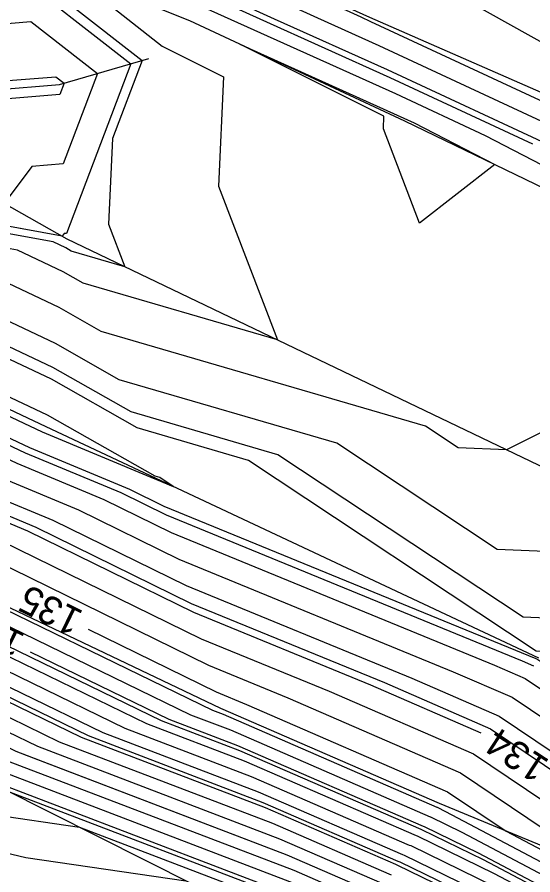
# Model space of a CAD drawing. Extents: x 2354170 to 2357230, y 866100 to 868290.
# Drawn here: x 2354998.2 to 2355034.8, y 867572.5 to 867633.4 of the extents above; entities that cross this region are included whole.
import ezdxf

# ---------------------------------------------------------------- set-up
doc = ezdxf.new("R2010")
doc.units = 0
for name, color, linetype in [('Default', 7, 'Continuous'), ('DTM Contours Major', 7, 'Continuous'), ('DTM Contours Major Text', 7, 'Continuous'), ('DTM Contours Minor', 7, 'Continuous'), ('PH Exist DTM Breakline', 7, 'Continuous')]:
    doc.layers.add(name, color=color, linetype=linetype)

msp = doc.modelspace()

# ---------------------------------------------------------------- linework, layer by layer
at = {"layer": 'Default'}
for points in [[(2355074.447, 867619.179), (2355074.154, 867619.39), (2355068.209, 867620.789), (2355051.797, 867622.962), (2355050.162, 867623.866), (2355048.755, 867624.16), (2355028.509, 867635.467), (2355025.079, 867637.946), (2355021.957, 867639.854), (2355009.227, 867645.813), (2355004.635, 867648.65), (2355001.188, 867649.633), (2354995.884, 867652.137), (2354991.371, 867653.721), (2354989.082, 867654.28), (2354986.916, 867655.031), (2354982.716, 867654.347)], [(2355046.588, 867622.223), (2355023.336, 867633.042), (2355022.638, 867633.357), (2355002.267, 867642.626), (2355001.673, 867642.728), (2354993.045, 867646.364), (2354992.846, 867646.429), (2354988.085, 867647.906), (2354983.375, 867649.109), (2354983.243, 867649.088), (2354977.432, 867648.175), (2354973.782, 867647.262), (2354972.722, 867647.082), (2354969.898, 867645.517), (2354967.05, 867643.227), (2354964.198, 867641.826), (2354961.475, 867638.94), (2354959.64, 867637.119), (2354958.142, 867634.538), (2354957.683, 867633.811), (2354956.183, 867632.466)], [(2355041.545, 867623.135), (2355023.921, 867631.335), (2355019.568, 867633.296), (2355004.341, 867640.224), (2354999.614, 867641.037), (2354994.549, 867643.171), (2354990.259, 867644.558), (2354987.614, 867645.379), (2354984.997, 867646.047), (2354979.583, 867645.201), (2354977.773, 867644.916), (2354976.636, 867644.632), (2354972.157, 867643.873), (2354971.277, 867643.386), (2354970.39, 867642.673), (2354964.682, 867639.867), (2354963.344, 867638.45), (2354960.556, 867635.683), (2354959.708, 867634.22), (2354959.07, 867633.211), (2354956.993, 867631.348), (2354956.996, 867631.345), (2354956.983, 867631.341), (2354954.713, 867627.551)], [(2354986.75, 867624.248), (2354986.725, 867624.257), (2354980.026, 867631.929), (2354978.413, 867633.662), (2354976.726, 867638.904), (2354979.353, 867640.37), (2354983.475, 867638.012), (2354989.184, 867636.062), (2354993.744, 867634.034), (2354996.674, 867632.856), (2354999.209, 867633.063), (2355003.943, 867629.367), (2355001.505, 867622.952), (2354999.284, 867622.77), (2354997.33, 867620.144), (2354990.982, 867621.302), (2354986.75, 867624.248)], [(2355094.488, 867599.695), (2355088.709, 867601.999), (2355088.596, 867602.001), (2355075.753, 867605.694), (2355071.157, 867607.685), (2355062.985, 867611.611), (2355055.759, 867614.57), (2355048.746, 867617.693), (2355036.501, 867624.046), (2355024.505, 867629.627), (2355016.498, 867633.235), (2355006.415, 867637.823), (2355002.615, 867638.476)], [(2354997.435, 867636.982), (2355006.309, 867630.054), (2355001.739, 867618.031), (2355001.576, 867618.017), (2355001.433, 867617.825), (2354989.535, 867619.995), (2354985.973, 867622.475), (2354979.191, 867624.914), (2354977.85, 867626.449), (2354973.891, 867630.702), (2354972.606, 867634.697)], [(2355001.875, 867636.557), (2355008.523, 867631.3), (2355012.868, 867629.131), (2355012.524, 867621.386), (2355016.711, 867610.469), (2355002.933, 867614.49), (2355001.503, 867615.301), (2354998.259, 867616.833), (2354988.089, 867618.688), (2354985.195, 867620.702), (2354977.975, 867623.299), (2354976.56, 867623.87), (2354969.645, 867627.446), (2354969.37, 867627.742), (2354969.311, 867627.925), (2354968.973, 867628.061), (2354968.6, 867627.905), (2354962.364, 867630.556), (2354957.519, 867629.22), (2354955.803, 867626.354)], [(2355048.215, 867616.263), (2355031.457, 867624.957), (2355025.09, 867627.92), (2355013.429, 867633.173), (2355008.489, 867635.421)], [(2354992.429, 867622.609), (2354991.895, 867622.981), (2354990.502, 867629.161), (2354987.448, 867632.321), (2354990.911, 867631.138), (2354991.673, 867630.799), (2354996.664, 867628.791), (2355000.982, 867629.144), (2355001.578, 867628.679), (2355001.271, 867627.873), (2354996.992, 867627.523), (2354993.227, 867622.463), (2354992.429, 867622.609)], [(2354959.634, 867630.938), (2354957.251, 867630.281), (2354955.258, 867626.952), (2354953.783, 867625.062), (2354954.084, 867622.102), (2354955.041, 867618.903), (2354957.909, 867617.517), (2354960.067, 867614.856), (2354961.724, 867613.947), (2354967.292, 867612.723), (2354969.1, 867611.433), (2354973.288, 867608.551), (2354977.275, 867607.102), (2354987.83, 867602.007), (2354995.52, 867598.375), (2354998.973, 867596.937), (2355010.76, 867591.157), (2355023.311, 867586.01), (2355031.132, 867582.608)], [(2355014.031, 867631.458), (2355025.674, 867626.212), (2355026.413, 867625.868), (2355032.114, 867622.911), (2355026.788, 867618.75), (2355024.217, 867625.454), (2355024.256, 867626.353), (2355014.031, 867631.458)], [(2355045.465, 867608.937), (2355032.951, 867602.68), (2355029.511, 867602.827), (2355027.201, 867604.358), (2355004.209, 867611.068), (2355001.226, 867612.759), (2354994.46, 867615.955), (2354986.642, 867617.381), (2354984.418, 867618.929), (2354978.867, 867620.925), (2354975.565, 867622.258), (2354969.801, 867625.239), (2354968.438, 867626.322), (2354967.611, 867626.832), (2354961.851, 867629.28), (2354957.788, 867628.16), (2354956.348, 867625.755)], [(2355039.634, 867595.298), (2355032.282, 867595.611), (2355020.924, 867603.141), (2355005.486, 867607.647), (2355000.95, 867610.217), (2354990.661, 867615.077), (2354985.195, 867616.074), (2354983.64, 867617.156), (2354979.76, 867618.552), (2354974.57, 867620.647), (2354970.483, 867622.761), (2354967.689, 867624.981), (2354965.992, 867626.027), (2354961.339, 867628.004), (2354958.056, 867627.099), (2354956.893, 867625.157), (2354956.032, 867624.053)], [(2354959.297, 867626.307), (2354958.324, 867626.038), (2354957.438, 867624.558), (2354956.782, 867623.717), (2354956.916, 867622.401), (2354957.342, 867620.978), (2354961.864, 867618.793), (2354962.775, 867617.67), (2354963.474, 867617.287), (2354970.863, 867615.663), (2354971.341, 867615.322), (2354972.448, 867614.56), (2354980.701, 867611.562), (2354983.324, 867610.296), (2354999.117, 867602.837), (2355006.207, 867599.884), (2355008.646, 867598.688), (2355035.042, 867587.863), (2355035.182, 867587.803), (2355035.537, 867587.564), (2355042.462, 867583.632)], [(2355055.077, 867585.745), (2355036.484, 867587.97), (2355035.529, 867588.375), (2355035.053, 867588.395), (2355014.646, 867601.924), (2355006.762, 867604.225), (2355000.673, 867607.676), (2354986.861, 867614.199), (2354983.748, 867614.767), (2354982.863, 867615.384), (2354980.653, 867616.178), (2354973.576, 867619.035), (2354971.166, 867620.282), (2354966.939, 867623.64), (2354964.849, 867624.927)], [(2354956.208, 867622.326), (2354956.766, 867620.459), (2354960.875, 867618.474), (2354962.098, 867616.967), (2354963.036, 867616.452), (2354969.971, 867614.928), (2354970.781, 867614.35), (2354972.658, 867613.057), (2354979.844, 867610.447), (2354984.451, 867608.223), (2354998.218, 867601.721), (2355004.398, 867599.147), (2355009.175, 867596.805), (2355032.109, 867587.4), (2355034.266, 867586.462), (2355039.748, 867582.774)], [(2354956.191, 867619.94), (2354959.887, 867618.155), (2354961.421, 867616.263), (2354962.599, 867615.617), (2354969.078, 867614.193), (2354970.221, 867613.378), (2354972.868, 867611.555), (2354978.988, 867609.332), (2354985.577, 867606.151), (2354997.319, 867600.606), (2355002.59, 867598.411), (2355009.703, 867594.923), (2355029.176, 867586.937), (2355033.351, 867585.121), (2355043.958, 867577.984)], [(2354955.616, 867619.421), (2354958.898, 867617.836), (2354960.744, 867615.56), (2354962.161, 867614.782), (2354968.185, 867613.458), (2354969.66, 867612.406), (2354973.078, 867610.053), (2354978.132, 867608.217), (2354986.703, 867604.079), (2354996.419, 867599.49), (2355000.781, 867597.674), (2355010.232, 867593.04), (2355026.243, 867586.473), (2355032.436, 867583.78), (2355048.169, 867573.195)], [(2354954.466, 867618.384), (2354956.92, 867617.199), (2354959.39, 867614.152), (2354961.286, 867613.112), (2354966.399, 867611.988), (2354968.54, 867610.461), (2354973.497, 867607.048), (2354976.419, 867605.987), (2354988.956, 867599.935), (2354994.621, 867597.259), (2354997.164, 867596.2), (2355011.289, 867589.274), (2355020.378, 867585.547), (2355030.605, 867581.098), (2355048.031, 867569.375)], [(2354955.931, 867616.88), (2354958.713, 867613.449), (2354960.849, 867612.277), (2354965.507, 867611.253), (2354967.979, 867609.489), (2354973.707, 867605.546), (2354975.562, 867604.872), (2354990.082, 867597.863), (2354993.722, 867596.144), (2354995.356, 867595.463), (2355011.818, 867587.391), (2355017.445, 867585.084), (2355029.69, 867579.758), (2355040.479, 867572.499)], [(2354952.964, 867615.923), (2354956.682, 867611.338), (2354959.536, 867609.773), (2354962.828, 867609.049), (2354966.298, 867606.573), (2354972.338, 867602.415), (2354973.485, 867601.633), (2354989.329, 867593.971), (2354992.273, 867592.763), (2355010.547, 867583.886), (2355013.364, 867582.809), (2355027.534, 867576.646), (2355027.566, 867576.634), (2355029.785, 867575.552), (2355051.989, 867563.822)], [(2354953.953, 867616.242), (2354957.359, 867612.042), (2354959.973, 867610.607), (2354963.721, 867609.784), (2354966.859, 867607.545), (2354973.714, 867602.825), (2354973.951, 867602.664), (2354991.637, 867594.111), (2354992.134, 867593.907), (2355012.097, 867584.209), (2355012.864, 867583.916), (2355028.02, 867577.324), (2355028.029, 867577.321), (2355028.633, 867577.026), (2355052.315, 867564.516)], [(2354982.198, 867612.368), (2355000.016, 867603.952), (2355008.015, 867600.621), (2355008.118, 867600.571), (2355009.313, 867600.081), (2355008.369, 867600.707), (2355008.039, 867600.803), (2355000.396, 867605.134), (2354983.062, 867613.321)], [(2355051.339, 867562.435), (2355032.089, 867572.605), (2355026.64, 867575.26), (2355026.562, 867575.29), (2355014.364, 867580.596), (2355007.447, 867583.239), (2354992.549, 867590.476), (2354984.713, 867593.692), (2354972.553, 867599.572), (2354969.586, 867601.594), (2354965.178, 867604.629), (2354961.043, 867607.579), (2354958.661, 867608.103), (2354955.328, 867609.931)], [(2355033.241, 867571.131), (2355026.177, 867574.573), (2355026.076, 867574.612), (2355014.864, 867579.489), (2355005.897, 867582.915), (2354992.688, 867589.332), (2354982.405, 867593.552), (2354972.087, 867598.541), (2354968.21, 867601.184), (2354964.618, 867603.657), (2354960.15, 867606.844), (2354958.223, 867607.268), (2354954.651, 867609.227)], [(2355034.393, 867569.657), (2355025.715, 867573.886), (2355025.59, 867573.934), (2355015.365, 867578.382), (2355004.347, 867582.591), (2354992.826, 867588.188), (2354980.097, 867593.412), (2354971.622, 867597.511), (2354966.834, 867600.773), (2354964.057, 867602.685), (2354959.257, 867606.109), (2354957.786, 867606.433), (2354953.974, 867608.524)], [(2355024.789, 867572.512), (2355024.618, 867572.579), (2355016.365, 867576.168), (2355001.247, 867581.944), (2354993.103, 867585.901), (2354975.481, 867593.133), (2354970.69, 867595.449), (2354964.082, 867599.952), (2354962.937, 867600.741), (2354957.472, 867604.64), (2354956.911, 867604.763)], [(2355024.132, 867571.901), (2355016.865, 867575.061), (2354999.697, 867581.621), (2354993.241, 867584.757), (2354973.173, 867592.993), (2354970.224, 867594.419), (2354962.706, 867599.542), (2354962.376, 867599.768), (2354956.579, 867603.905), (2354956.473, 867603.928)], [(2354954.687, 867593.733), (2354960.394, 867594.275), (2354966.575, 867592.286), (2354968.527, 867591.895), (2354969.553, 867591.672), (2354970.22, 867591.518), (2354970.695, 867591.406), (2354973.841, 867590.545), (2354993.518, 867582.469), (2354996.597, 867580.974), (2355017.865, 867572.848), (2355023.16, 867570.545)], [(2354972.811, 867592.054), (2354993.379, 867583.613), (2354998.147, 867581.297), (2355017.365, 867573.955), (2355023.646, 867571.223), (2355023.864, 867571.138), (2355039.001, 867563.761), (2355049.388, 867558.274), (2355054.316, 867556.436), (2355064.534, 867552.462)], [(2354956.087, 867590.967), (2354959.284, 867591.078), (2354959.294, 867591.079), (2354959.305, 867591.076), (2354966.144, 867589.706), (2354969.74, 867588.924), (2354972.078, 867588.385), (2354973.744, 867587.993), (2354984.768, 867584.973), (2354993.656, 867581.326), (2354995.047, 867580.65), (2355018.365, 867571.741)], [(2355003.273, 867589.958), (2355012.346, 867585.508), (2355014.512, 867584.62), (2355028.775, 867578.417), (2355032.927, 867575.623), (2355052.64, 867565.209), (2355064.575, 867560.758), (2355069.477, 867558.851), (2355085.298, 867551.851), (2355086.723, 867551.29), (2355093.921, 867548.105)], [(2355079.464, 867548.694), (2355070.954, 867552.459), (2355057.393, 867557.732), (2355050.364, 867560.354), (2355035.545, 867568.183), (2355025.252, 867573.199), (2355025.104, 867573.257), (2355015.865, 867577.275), (2355002.797, 867582.268), (2354992.964, 867587.044), (2354988.082, 867589.048)], [(2354999.161, 867588.34), (2355008.997, 867583.562), (2355013.864, 867581.702), (2355027.048, 867575.968), (2355027.103, 867575.947), (2355030.937, 867574.078), (2355051.664, 867563.128), (2355061.497, 867559.461), (2355070.11, 867556.112), (2355083.646, 867550.122), (2355086.139, 867549.14), (2355090.249, 867547.322)], [(2354975.638, 867584.852), (2354976.793, 867584.58), (2354992.187, 867580.363), (2354993.065, 867580.122), (2354993.602, 867579.987), (2354993.946, 867579.903), (2354994.183, 867579.846), (2354995.101, 867579.713), (2355018.865, 867570.634), (2355022.188, 867569.189), (2355022.475, 867569.077), (2355042.456, 867559.34), (2355048.413, 867556.193), (2355051.238, 867555.139), (2355068.491, 867548.43)], [(2354996.524, 867576.797), (2355002.655, 867575.912), (2355019.366, 867569.527)], [(2354980.044, 867572.352), (2354981.509, 867572.931), (2354982.367, 867573.446), (2354983.675, 867574.675), (2354984.218, 867575.219), (2354984.482, 867575.423), (2354984.731, 867575.596), (2354986.279, 867576.049), (2354987.13, 867576.29), (2354987.467, 867576.244), (2354988.516, 867576.291), (2354991.698, 867575.49), (2354995.945, 867574.446), (2354998.866, 867573.748), (2355010.208, 867572.11)]]:
    msp.add_lwpolyline(points, dxfattribs=at)
at = {"layer": 'DTM Contours Major'}
for points in [[(2355074.447, 867619.179), (2355074.154, 867619.39), (2355068.209, 867620.789), (2355051.797, 867622.962), (2355050.162, 867623.866), (2355048.755, 867624.16), (2355028.509, 867635.467), (2355025.079, 867637.946), (2355021.957, 867639.854), (2355009.227, 867645.813), (2355004.635, 867648.65), (2355001.188, 867649.633), (2354995.884, 867652.137), (2354991.371, 867653.721), (2354989.082, 867654.28), (2354986.916, 867655.031), (2354982.716, 867654.347)], [(2355003.273, 867589.958), (2355012.346, 867585.508), (2355014.512, 867584.62), (2355028.775, 867578.417), (2355032.927, 867575.623), (2355052.64, 867565.209), (2355064.575, 867560.758), (2355069.477, 867558.851), (2355085.298, 867551.851), (2355086.723, 867551.29), (2355093.921, 867548.105)]]:
    msp.add_lwpolyline(points, dxfattribs=at)
at = {"layer": 'DTM Contours Minor'}
for points in [[(2355034.82, 867624.35), (2355024.7, 867629.058), (2355015.475, 867633.214), (2355007.106, 867637.022), (2354996.869, 867638.781), (2354996.555, 867638.913), (2354991.72, 867640.477), (2354996.506, 867638.348), (2354996.687, 867638.275), (2354996.844, 867638.288), (2355007.098, 867630.283), (2355004.999, 867624.763), (2355004.729, 867618.674), (2355005.884, 867615.662), (2355002.082, 867616.771), (2355001.687, 867616.995), (2355000.792, 867617.418), (2354989.053, 867619.559), (2354985.714, 867621.884), (2354977.379, 867624.881), (2354977.223, 867624.944), (2354976.456, 867625.34), (2354975.625, 867626.234)], [(2354980.027, 867617.102), (2354973.907, 867619.572), (2354970.938, 867621.108), (2354967.189, 867624.087), (2354964.912, 867625.49), (2354960.997, 867627.154), (2354958.235, 867626.392), (2354957.256, 867624.758), (2354956.532, 867623.829), (2354956.68, 867622.376), (2354957.15, 867620.805), (2354961.535, 867618.687), (2354962.549, 867617.436), (2354963.328, 867617.009), (2354970.566, 867615.418), (2354971.154, 867614.998), (2354972.518, 867614.059), (2354980.415, 867611.19), (2354983.7, 867609.605), (2354998.817, 867602.465), (2355005.604, 867599.639), (2355008.822, 867598.061), (2355034.064, 867587.709), (2355034.877, 867587.356)], [(2355051.556, 867562.897), (2355031.321, 867573.587), (2355026.949, 867575.718), (2355026.886, 867575.742), (2355014.031, 867581.333), (2355008.48, 867583.454), (2354992.457, 867591.238), (2354986.252, 867593.785), (2354972.864, 867600.259), (2354970.503, 867601.868), (2354965.551, 867605.277), (2354961.638, 867608.069), (2354958.952, 867608.659), (2354955.779, 867610.4), (2354951.646, 867615.498), (2354951.398, 867615.617), (2354950.441, 867618.82), (2354949.241, 867621.111), (2354949.099, 867621.675)], [(2354955.233, 867619.076), (2354958.238, 867617.624), (2354960.293, 867615.091), (2354961.869, 867614.226), (2354967.59, 867612.968), (2354969.287, 867611.757), (2354973.218, 867609.051), (2354977.561, 867607.474), (2354987.454, 867602.698), (2354995.82, 867598.747), (2354999.576, 867597.183), (2355010.584, 867591.785), (2355024.288, 867586.165), (2355031.826, 867582.886), (2355050.977, 867570.001)], [(2355152.512, 867567.981), (2355134.902, 867576.713), (2355127.278, 867579.875), (2355126.516, 867580.24), (2355119.731, 867583.497), (2355106.992, 867590.341), (2355101.553, 867592.354), (2355097.264, 867595.078), (2355090.882, 867596.12), (2355088.741, 867596.974), (2355084.875, 867597.032), (2355084.112, 867597.251), (2355080.993, 867598.602), (2355072.97, 867589.975), (2355068.833, 867583.626), (2355058.619, 867586.396), (2355042.447, 867588.331), (2355036.897, 867590.683), (2355034.129, 867590.8), (2355016.739, 867602.33), (2355006.337, 867605.365), (2355000.765, 867608.523), (2354988.128, 867614.492), (2354985.563, 867614.96)], [(2355123.364, 867530.551), (2355115.004, 867534.055), (2355112.94, 867534.872), (2355101.56, 867539.374), (2355085.425, 867546.513), (2355081.628, 867548.01), (2355070.884, 867552.763), (2355057.735, 867557.876), (2355050.472, 867560.586), (2355035.161, 867568.674), (2355025.406, 867573.428), (2355025.266, 867573.483), (2355015.698, 867577.644), (2355003.313, 867582.376), (2354992.918, 867587.426), (2354978.558, 867593.319), (2354971.311, 867596.824), (2354965.917, 867600.499), (2354963.684, 867602.037), (2354958.662, 867605.619), (2354957.494, 867605.876), (2354953.523, 867608.055)], [(2354998.582, 867581.131), (2355017.365, 867573.955), (2355023.646, 867571.223), (2355023.864, 867571.138), (2355039.001, 867563.761), (2355049.388, 867558.274), (2355054.316, 867556.436), (2355071.587, 867549.719), (2355079.792, 867546.089), (2355084.776, 867544.124), (2355097.397, 867538.54), (2355112.314, 867532.638), (2355115.02, 867531.568), (2355127.461, 867526.353), (2355139.747, 867522.851), (2355142.992, 867521.452), (2355157.676, 867515.384), (2355166.814, 867511.446), (2355180.204, 867505.527), (2355182.997, 867504.246)], [(2354997.619, 867578.446), (2355019.032, 867570.265)]]:
    msp.add_lwpolyline(points, dxfattribs=at)
at = {"layer": 'PH Exist DTM Breakline'}
for points in [[(2354950.702, 867629.187), (2354951.43, 867630.832), (2354954.125, 867635.352), (2354957.876, 867639.883), (2354963.714, 867643.781), (2354969.11, 867646.734), (2354972.897, 867648.077), (2354977.351, 867648.954), (2354983.334, 867649.185), (2354988.141, 867648.209), (2354992.972, 867646.52), (2355001.969, 867642.971), (2355023.225, 867633.369), (2355050.188, 867621.573)], [(2355047.856, 867615.298), (2355025.751, 867625.988), (2355010.481, 867633.114), (2354996.688, 867638.633), (2354987.026, 867642.219), (2354977.927, 867643.442), (2354971.901, 867642.422), (2354975.162, 867639.949), (2354981.522, 867635.698), (2354991.257, 867630.149), (2354996.663, 867628.206), (2355001.237, 867628.58), (2355007.575, 867630.422)], [(2354971.901, 867642.422), (2354965.149, 867637.977), (2354961.754, 867633.806), (2354960.882, 867632.426), (2354962.631, 867631.222), (2354969.152, 867627.599), (2354977.305, 867625.078), (2354986.753, 867624.254), (2354992.637, 867622.797), (2355001.758, 867617.641), (2355041.562, 867598.55)], [(2354960.882, 867632.426), (2354956.982, 867631.345), (2354953.002, 867629.43), (2354950.595, 867626.491), (2354949.944, 867621.665), (2354951.054, 867615.307), (2354953.445, 867607.974), (2354956.371, 867603.734), (2354962.15, 867599.376), (2354969.478, 867592.769), (2354993.77, 867580.383), (2355020.895, 867566.731)], [(2355035.245, 867587.895), (2355000.307, 867604.313), (2354981.834, 867613.038), (2354972.146, 867616.719), (2354964.751, 867619.724), (2354959.184, 867622.64)], [(2355028.202, 867577.578), (2355012.677, 867584.33), (2354992.106, 867594.139), (2354974.072, 867602.932)], [(2355219.015, 867495.786), (2355180.571, 867514.321), (2355138.993, 867532.299), (2355114.953, 867542.057), (2355068.64, 867562.47), (2355053.527, 867567.101), (2355028.202, 867577.578)]]:
    msp.add_lwpolyline(points, dxfattribs=at)

# ---------------------------------------------------------------- texts
at = {"layer": 'Default'}
for s, rotation, p in [('135', 153.879, (2355003.034, 867591.188)), ('136', 154.08944, (2354998.918, 867589.57)), ('134', 146.80037, (2355036.083, 867580.609))]:
    msp.add_text(s, height=2, rotation=rotation, dxfattribs=at).set_placement(p)
at = {"layer": 'DTM Contours Major Text'}
msp.add_text('135', height=2, rotation=153.879, dxfattribs=at).set_placement((2355003.034, 867591.188))

doc.saveas('drawing.dxf')
